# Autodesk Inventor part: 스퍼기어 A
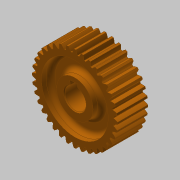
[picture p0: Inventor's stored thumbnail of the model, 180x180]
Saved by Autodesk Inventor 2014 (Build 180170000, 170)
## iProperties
Created: 2020-04
Part Number: 스퍼기어 A
Material: Steel
Document SubType Name: Modeling
Designer: mduedu
Categories: <?xml version="1.0" encoding="UTF-16"?> <MemberInstance><Categories><FamilyTemplate><FamilyTemplateParameter ValueType="xs:double" Id="1" ObjectReferenceKey="da
Density: 7.85 g/cm^3
Mass: 238.005 g
Surface Area: 130.635 cm^2
Volume: 30.3191 cm^3
Appearance: Orange
CustomPartVersion: 1
Author: mduedu
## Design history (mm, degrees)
sketch "Sketch1"
  geometry: C1 r 28.2 at (0, 0)
  constraints: 1 centre point
  dimensions: "d0" = 56.4 diameter of C1 (= da_da)
extrude "Extrusion1" new body sketch "Sketch1" distance "d1" = 20 (= da_b); taper "d2" = 0 deg
workplane "Work Plane2"
sketch "Sketch2"
  geometry: C1 r 28.2 at (0, 0) reference; C2 r 27 at (0, 0)
  constraints: 1 centre point, 1 coincident
  dimensions: "d3" = 54 diameter of C2 (= da_dw)
feature "피치 지름" sketch "Sketch2" dims "d4" = 10, "d5" = 0
workplane "Work Plane8"
workplane "Work Plane9"
feature "스퍼 기어" dims "da_b" = 20, "da_d" = 54, "da_aw" = 45, "da_da" = 56.4, "da_df" = 51.129, "da_dw" = 54, angle "da_beta" = 0 deg, "da_lefttooth" = 0, "da_righttooth" = 0
node "작업 평면11"
sketch "스케치3"
  geometry: C1 r 12 at (0, 0); C2 r 22 at (0, 0); 1 further point
  constraints: 2 centre point, 2 coincident
  dimensions: "d49" = 24 diameter of C1; "d50" = 44 diameter of C2
extrude "돌출2" cut sketch "스케치3" distance "d51" = 6; taper "d52" = 0 deg
fillet "모깎기1" dims "d53" = 3
sketch "스케치4" dims "d17" = 0
  geometry: L1 (-3.06, 6.296)-(1.921, 6.731); L2 (1.921, 6.731)-(1.68, 9.483); L3 (1.68, 9.483)-(-3.301, 9.047); L4 (-3.301, 9.047)-(-3.06, 6.296); L5 (-3.728, 42.608)-(3.728, -42.608) reference; A1 r 7 centre (0, 0) between (-3.06, 6.296) and (1.921, 6.731); 1 further point
  constraints: 8 end point, 4 perpendicular, 2 point on circle, 1 centre point, 1 coincident
  dimensions: "d54" = 14 diameter of A1; "d63" = 16.3 dimension on A1 L3; "d64" = 5 distance of L2.end L3.end
extrude "돌출3" cut sketch "스케치4" stored distance "d58" = 6; taper "d59" = 0 deg
chamfer "모따기1" distance "d60" = 0.5; stored, may be unused: second distance "d61" = 2, angle "d62" = 45 deg
body "Solid1"
mirror "대칭1"
body "Srf1"
other parameters: "d16" = 45 (= da_aw), "d34" = 5 deg (computed from da_z), "d39" = 0, "d41" = 0, "d43" = 45 (= da_aw), "d46" = 45 (= da_aw), "d47" = 0, "d48" = 0
